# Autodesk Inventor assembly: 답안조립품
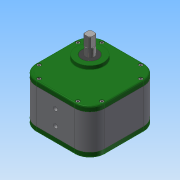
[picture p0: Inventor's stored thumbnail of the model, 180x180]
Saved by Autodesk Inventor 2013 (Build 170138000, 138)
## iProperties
Created: 2017-08
Part Number: 답안조립품
Document SubType Name: Assembly
Designer: Administrator
Author: Administrator
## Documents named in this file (11)
- C:\Users\Administrator\Desktop\371108V1009\답안조립품.iam
- C:\Users\Administrator\Desktop\371108V1009\본체.ipt
- C:\Users\Administrator\Desktop\371108V1009\뒤커버.ipt
- C:\Users\Administrator\Desktop\371108V1009\메인축.ipt
- C:\Users\Administrator\Desktop\371108V1009\베어링 608.ipt
- C:\Users\Administrator\Desktop\371108V1009\서브축.ipt
- C:\Users\Administrator\Desktop\371108V1009\오일실 8 22 7.ipt
- C:\Users\Administrator\Desktop\371108V1009\베어링 6003.ipt
- C:\Users\Administrator\Desktop\371108V1009\앞커버.ipt
- C:\Users\Administrator\Desktop\371108V1009\볼트 M4.ipt
- C:\Users\Administrator\Desktop\371108V1009\오일실 17 32 8.ipt
